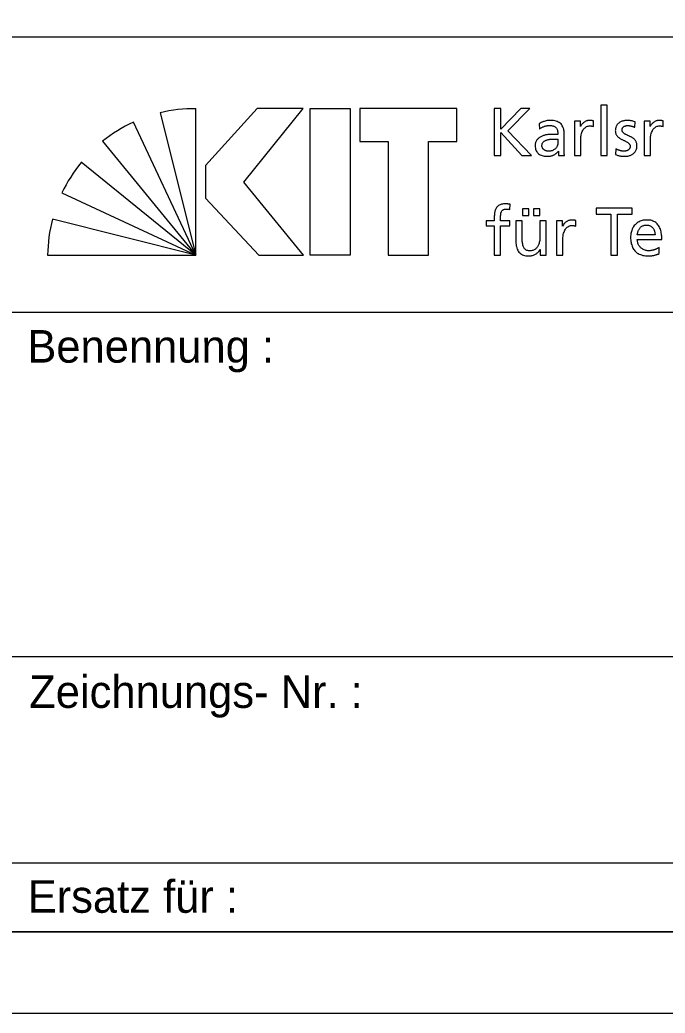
# Model space of a CAD drawing. Extents: x 0 to 594, y 0 to 420.
# Drawn here: x 550.33 to 570.16, y 0 to 30.52 of the extents above; entities that cross this region are included whole.
import ezdxf

# ---------------------------------------------------------------- set-up
doc = ezdxf.new("R2010")
doc.units = 0
doc.layers.add('90_Plankopf', color=7, linetype='Continuous')

msp = doc.modelspace()

# ---------------------------------------------------------------- linework, layer by layer
at = {"layer": '90_Plankopf'}
for p, q in [((503.06, 29.995), (592, 29.995)), ((503.06, 29.995), (592, 29.995)), ((555.74, 23.293), (555.74, 27.792)), ((564.905, 27.793), (564.905, 26.353)), ((554.637, 27.666), (555.74, 23.293)), ((555.74, 23.293), (553.817, 27.376)), ((566.29, 27.331), (566.3, 27.166)), ((567.963, 27.242), (567.963, 27.416)), ((569.228, 27.22), (569.245, 27.389)), ((570.106, 27.242), (570.106, 27.416)), ((567.059, 26.559), (567.059, 26.995)), ((552.872, 26.793), (555.74, 23.293)), ((566.865, 26.854), (566.865, 26.761)), ((568.649, 26.559), (568.638, 26.386)), ((564.905, 26.353), (565.111, 26.353)), ((565.753, 26.353), (566.054, 26.353)), ((555.74, 23.293), (552.217, 26.143)), ((551.62, 25.207), (555.74, 23.293)), ((565.387, 24.696), (565.395, 24.853)), ((555.74, 23.293), (551.329, 24.394)), ((567.413, 24.182), (567.413, 24.356)), ((569.853, 23.92), (569.308, 23.92)), ((569.308, 23.776), (570.059, 23.776)), ((569.979, 23.337), (569.979, 23.53)), ((551.182, 23.293), (555.74, 23.293)), ((550, 21.535), (592, 21.535)), ((550, 10.96), (592, 10.96)), ((550, 4.615), (592, 4.615)), ((592, 2.5), (503.06, 2.5)), ((508.9, 2.5), (592, 2.5)), ((508.9, 2.5), (592, 2.5))]:
    msp.add_line(p, q, dxfattribs=at)
for points in [[(0, 0), (594.5, 0), (594.5, 420.5), (0, 420.5)], [(12.5, 2.5), (592, 2.5), (592, 418), (12.5, 418)], [(559.033, 27.793), (557.618, 27.793), (556.036, 26.049), (556.036, 25.046), (557.669, 23.293), (559.042, 23.293), (557.211, 25.531)], [(560.485, 27.793), (560.485, 23.293), (559.251, 23.293), (559.251, 27.793)], [(560.781, 27.793), (560.781, 26.78), (561.651, 26.78), (561.651, 23.293), (562.885, 23.293), (562.885, 26.78), (563.755, 26.78), (563.755, 27.793)]]:
    msp.add_lwpolyline(points, close=True, dxfattribs=at)
for points in [[(566.054, 26.353), (565.324, 27.112), (566, 27.793), (565.726, 27.793), (565.111, 27.16), (565.111, 27.793), (564.905, 27.793)], [(568.19, 26.353), (568.384, 26.353), (568.384, 27.9), (568.19, 27.9), (568.19, 26.353)], [(567.561, 27.242), (567.557, 27.242), (567.557, 27.405), (567.375, 27.405), (567.375, 26.353), (567.569, 26.353), (567.569, 26.832)], [(569.703, 27.242), (569.699, 27.242), (569.699, 27.405), (569.518, 27.405), (569.518, 26.353), (569.712, 26.353), (569.712, 26.832)], [(565.111, 26.353), (565.111, 27.059), (565.753, 26.353)], [(566.882, 26.489), (566.886, 26.489), (566.886, 26.353), (567.067, 26.353)], [(568.495, 23.293), (568.701, 23.293), (568.701, 24.552), (569.149, 24.552), (569.149, 24.733), (568.047, 24.733), (568.047, 24.552), (568.495, 24.552), (568.495, 23.293)], [(564.912, 24.443), (564.912, 24.346), (564.665, 24.346), (564.665, 24.189), (564.912, 24.189), (564.912, 23.293), (565.106, 23.293), (565.106, 24.189), (565.385, 24.189), (565.385, 24.346), (565.106, 24.346), (565.106, 24.459)], [(565.777, 24.713), (565.777, 24.506), (565.971, 24.506), (565.971, 24.713), (565.777, 24.713)], [(566.115, 24.713), (566.115, 24.506), (566.309, 24.506), (566.309, 24.713), (566.115, 24.713)], [(565.771, 23.801), (565.771, 24.346), (565.577, 24.346), (565.577, 23.72)], [(566.507, 23.293), (566.507, 24.346), (566.313, 24.346), (566.313, 23.859)], [(567.011, 24.182), (567.007, 24.182), (567.007, 24.346), (566.825, 24.346), (566.825, 23.293), (567.019, 23.293), (567.019, 23.772)], [(566.316, 23.46), (566.32, 23.46), (566.32, 23.293), (566.507, 23.293)]]:
    msp.add_lwpolyline(points, dxfattribs=at)
for centre, start, end in [((555.724, 23.028), 89.8053, 103.1895), ((555.831, 23.059), 115.0126, 128.3968), ((555.908, 23.131), 140.7898, 154.174), ((555.946, 23.219), 165.7222, 179.1064)]:
    msp.add_arc(centre, 4.764, start, end, dxfattribs=at)
for points in [[(567.059, 26.995), (567.06, 27.09), (567.045, 27.17), (567.017, 27.235), (566.988, 27.3), (566.942, 27.348), (566.88, 27.381), (566.817, 27.413), (566.736, 27.43), (566.636, 27.43), (566.569, 27.43), (566.507, 27.42), (566.449, 27.402), (566.391, 27.384), (566.338, 27.361), (566.29, 27.331)], [(566.3, 27.166), (566.326, 27.188), (566.356, 27.207), (566.39, 27.223), (566.423, 27.239), (566.458, 27.251), (566.495, 27.26), (566.532, 27.269), (566.568, 27.273), (566.605, 27.273), (566.67, 27.273), (566.721, 27.263), (566.759, 27.243), (566.797, 27.222), (566.824, 27.191), (566.841, 27.151), (566.858, 27.11), (566.865, 27.059), (566.865, 26.999)], [(567.963, 27.416), (567.95, 27.418), (567.937, 27.421), (567.925, 27.423), (567.912, 27.425), (567.899, 27.427), (567.885, 27.428), (567.871, 27.429), (567.854, 27.43), (567.835, 27.43), (567.798, 27.43), (567.761, 27.422), (567.726, 27.406), (567.691, 27.39), (567.659, 27.368), (567.63, 27.339), (567.601, 27.311), (567.578, 27.279), (567.561, 27.242)], [(567.569, 26.832), (567.569, 26.92), (567.581, 26.996), (567.605, 27.06), (567.629, 27.124), (567.662, 27.174), (567.705, 27.208), (567.747, 27.243), (567.798, 27.26), (567.856, 27.261), (567.873, 27.261), (567.89, 27.26), (567.909, 27.257), (567.927, 27.254), (567.945, 27.249), (567.963, 27.242)], [(569.245, 27.389), (569.207, 27.4), (569.169, 27.41), (569.13, 27.418), (569.091, 27.426), (569.049, 27.43), (569.004, 27.43), (568.951, 27.43), (568.903, 27.423), (568.858, 27.41), (568.813, 27.397), (568.774, 27.377), (568.74, 27.35), (568.706, 27.323), (568.68, 27.29), (568.661, 27.249), (568.642, 27.208), (568.632, 27.161), (568.632, 27.106), (568.632, 27.064), (568.641, 27.028), (568.658, 26.997), (568.674, 26.966), (568.695, 26.94), (568.723, 26.917), (568.75, 26.895), (568.779, 26.875), (568.812, 26.857), (568.844, 26.84), (568.876, 26.824), (568.909, 26.809), (568.941, 26.793), (568.971, 26.777), (568.998, 26.761), (569.025, 26.745), (569.047, 26.727), (569.063, 26.706), (569.079, 26.686), (569.088, 26.663), (569.088, 26.636), (569.088, 26.607), (569.082, 26.584), (569.07, 26.564), (569.058, 26.545), (569.042, 26.529), (569.022, 26.518), (569.003, 26.506), (568.982, 26.498), (568.959, 26.493), (568.935, 26.487), (568.912, 26.485), (568.89, 26.485), (568.871, 26.485), (568.847, 26.488), (568.82, 26.493), (568.792, 26.499), (568.763, 26.507), (568.733, 26.518), (568.703, 26.529), (568.675, 26.543), (568.649, 26.559)], [(568.638, 26.386), (568.683, 26.363), (568.73, 26.347), (568.779, 26.339), (568.828, 26.331), (568.877, 26.327), (568.927, 26.328), (568.975, 26.328), (569.02, 26.335), (569.064, 26.348), (569.107, 26.361), (569.147, 26.381), (569.181, 26.408), (569.216, 26.435), (569.243, 26.469), (569.264, 26.51), (569.284, 26.551), (569.294, 26.6), (569.295, 26.656), (569.294, 26.704), (569.286, 26.745), (569.269, 26.778), (569.253, 26.811), (569.231, 26.84), (569.204, 26.863), (569.177, 26.886), (569.147, 26.906), (569.115, 26.922), (569.083, 26.939), (569.05, 26.954), (569.018, 26.968), (568.986, 26.983), (568.956, 26.998), (568.929, 27.013), (568.902, 27.029), (568.88, 27.047), (568.864, 27.068), (568.847, 27.089), (568.839, 27.115), (568.838, 27.145), (568.839, 27.174), (568.848, 27.198), (568.865, 27.217), (568.882, 27.236), (568.904, 27.25), (568.932, 27.259), (568.96, 27.269), (568.991, 27.273), (569.024, 27.273), (569.036, 27.273), (569.051, 27.271), (569.069, 27.269), (569.088, 27.266), (569.107, 27.261), (569.127, 27.256), (569.148, 27.251), (569.167, 27.246), (569.185, 27.239), (569.203, 27.233), (569.217, 27.226), (569.228, 27.22)], [(570.106, 27.416), (570.092, 27.418), (570.079, 27.421), (570.067, 27.423), (570.055, 27.425), (570.041, 27.427), (570.027, 27.428), (570.013, 27.429), (569.997, 27.43), (569.978, 27.43), (569.94, 27.43), (569.904, 27.422), (569.868, 27.406), (569.833, 27.39), (569.801, 27.368), (569.773, 27.339), (569.744, 27.311), (569.721, 27.279), (569.703, 27.242)], [(569.712, 26.832), (569.712, 26.92), (569.724, 26.996), (569.747, 27.06), (569.771, 27.124), (569.804, 27.174), (569.847, 27.208), (569.89, 27.243), (569.94, 27.26), (569.998, 27.261), (570.015, 27.261), (570.033, 27.26), (570.051, 27.257), (570.07, 27.254), (570.088, 27.249), (570.106, 27.242)], [(566.865, 26.999), (566.84, 27), (566.817, 27.001), (566.795, 27.001), (566.773, 27.002), (566.751, 27.003), (566.729, 27.003), (566.708, 27.003), (566.684, 27.003), (566.659, 27.003), (566.618, 27.003), (566.576, 26.999), (566.531, 26.992), (566.487, 26.985), (566.443, 26.973), (566.4, 26.957), (566.358, 26.941), (566.319, 26.919), (566.284, 26.892), (566.25, 26.866), (566.222, 26.833), (566.201, 26.794), (566.181, 26.755), (566.171, 26.709), (566.17, 26.656), (566.171, 26.58), (566.187, 26.518), (566.219, 26.469), (566.252, 26.421), (566.297, 26.385), (566.355, 26.362), (566.413, 26.339), (566.479, 26.328), (566.556, 26.328), (566.6, 26.328), (566.64, 26.334), (566.675, 26.344), (566.71, 26.355), (566.741, 26.368), (566.768, 26.384), (566.795, 26.401), (566.818, 26.419), (566.837, 26.437), (566.855, 26.455), (566.87, 26.472), (566.882, 26.489)], [(566.865, 26.761), (566.865, 26.709), (566.854, 26.661), (566.832, 26.62), (566.81, 26.578), (566.777, 26.546), (566.733, 26.522), (566.69, 26.498), (566.636, 26.485), (566.572, 26.485), (566.55, 26.485), (566.527, 26.489), (566.504, 26.496), (566.481, 26.503), (566.46, 26.514), (566.441, 26.529), (566.422, 26.543), (566.406, 26.561), (566.394, 26.582), (566.383, 26.604), (566.377, 26.628), (566.376, 26.656), (566.377, 26.693), (566.386, 26.724), (566.404, 26.749), (566.422, 26.773), (566.446, 26.793), (566.475, 26.807), (566.503, 26.822), (566.534, 26.833), (566.567, 26.841), (566.6, 26.848), (566.632, 26.853), (566.663, 26.855), (566.694, 26.858), (566.72, 26.859), (566.741, 26.858), (566.762, 26.858), (566.783, 26.858), (566.803, 26.856), (566.824, 26.855), (566.845, 26.855), (566.865, 26.854)], [(567.067, 26.353), (567.066, 26.363), (567.065, 26.377), (567.063, 26.393), (567.062, 26.411), (567.061, 26.433), (567.061, 26.46), (567.06, 26.486), (567.059, 26.52), (567.059, 26.559)], [(565.395, 24.853), (565.375, 24.856), (565.355, 24.859), (565.334, 24.862), (565.312, 24.864), (565.29, 24.866), (565.265, 24.866), (565.194, 24.865), (565.135, 24.855), (565.089, 24.836), (565.043, 24.816), (565.007, 24.787), (564.981, 24.75), (564.955, 24.713), (564.937, 24.668), (564.927, 24.616), (564.917, 24.565), (564.912, 24.507), (564.912, 24.443)], [(565.106, 24.459), (565.106, 24.495), (565.108, 24.528), (565.112, 24.558), (565.116, 24.588), (565.125, 24.615), (565.137, 24.637), (565.15, 24.66), (565.169, 24.677), (565.194, 24.69), (565.219, 24.702), (565.252, 24.709), (565.294, 24.709), (565.311, 24.709), (565.328, 24.708), (565.344, 24.706), (565.361, 24.703), (565.375, 24.7), (565.387, 24.696)], [(567.413, 24.356), (567.4, 24.359), (567.387, 24.361), (567.375, 24.363), (567.363, 24.365), (567.349, 24.367), (567.335, 24.368), (567.321, 24.37), (567.304, 24.37), (567.286, 24.37), (567.248, 24.37), (567.212, 24.362), (567.176, 24.346), (567.141, 24.33), (567.109, 24.308), (567.081, 24.28), (567.052, 24.252), (567.029, 24.219), (567.011, 24.182)], [(567.019, 23.772), (567.02, 23.86), (567.032, 23.937), (567.055, 24.001), (567.079, 24.065), (567.112, 24.114), (567.155, 24.148), (567.198, 24.183), (567.248, 24.201), (567.306, 24.201), (567.323, 24.201), (567.341, 24.2), (567.359, 24.197), (567.378, 24.195), (567.396, 24.19), (567.413, 24.182)], [(570.059, 23.776), (570.06, 23.861), (570.052, 23.94), (570.036, 24.012), (570.02, 24.084), (569.995, 24.146), (569.959, 24.2), (569.923, 24.254), (569.875, 24.295), (569.815, 24.325), (569.756, 24.355), (569.682, 24.37), (569.595, 24.37), (569.52, 24.37), (569.453, 24.357), (569.392, 24.331), (569.332, 24.305), (569.28, 24.269), (569.237, 24.221), (569.194, 24.174), (569.16, 24.118), (569.137, 24.052), (569.114, 23.988), (569.102, 23.916), (569.102, 23.838), (569.102, 23.752), (569.113, 23.674), (569.134, 23.604), (569.156, 23.535), (569.19, 23.475), (569.234, 23.425), (569.279, 23.375), (569.335, 23.336), (569.404, 23.309), (569.473, 23.282), (569.553, 23.269), (569.647, 23.268), (569.704, 23.269), (569.753, 23.273), (569.793, 23.28), (569.834, 23.288), (569.869, 23.297), (569.898, 23.307), (569.928, 23.317), (569.954, 23.327), (569.979, 23.337)], [(569.308, 23.92), (569.312, 23.955), (569.32, 23.989), (569.332, 24.024), (569.344, 24.058), (569.361, 24.089), (569.384, 24.118), (569.406, 24.147), (569.434, 24.17), (569.469, 24.187), (569.503, 24.204), (569.543, 24.213), (569.591, 24.213), (569.633, 24.213), (569.67, 24.206), (569.702, 24.19), (569.735, 24.175), (569.762, 24.154), (569.785, 24.127), (569.807, 24.101), (569.824, 24.069), (569.835, 24.034), (569.847, 23.999), (569.853, 23.961), (569.853, 23.92)], [(566.313, 23.859), (566.313, 23.794), (566.307, 23.736), (566.295, 23.683), (566.282, 23.63), (566.263, 23.584), (566.236, 23.546), (566.21, 23.507), (566.177, 23.478), (566.137, 23.457), (566.096, 23.436), (566.049, 23.426), (565.994, 23.425), (565.938, 23.429), (565.893, 23.444), (565.861, 23.473), (565.828, 23.501), (565.805, 23.542), (565.791, 23.597), (565.777, 23.651), (565.771, 23.719), (565.771, 23.801)], [(565.577, 23.72), (565.577, 23.626), (565.591, 23.545), (565.618, 23.478), (565.646, 23.41), (565.69, 23.359), (565.748, 23.323), (565.806, 23.287), (565.88, 23.269), (565.971, 23.268), (566.02, 23.269), (566.068, 23.276), (566.113, 23.291), (566.158, 23.307), (566.198, 23.329), (566.233, 23.357), (566.268, 23.386), (566.296, 23.42), (566.316, 23.46)], [(569.979, 23.53), (569.967, 23.521), (569.949, 23.51), (569.926, 23.497), (569.903, 23.485), (569.877, 23.474), (569.847, 23.463), (569.817, 23.452), (569.786, 23.443), (569.753, 23.436), (569.72, 23.429), (569.687, 23.426), (569.655, 23.425), (569.608, 23.426), (569.565, 23.434), (569.523, 23.451), (569.482, 23.468), (569.445, 23.492), (569.413, 23.523), (569.38, 23.554), (569.355, 23.59), (569.336, 23.633), (569.318, 23.676), (569.309, 23.724), (569.308, 23.776)]]:
    msp.add_open_spline(points, degree=3, dxfattribs=at)

# ---------------------------------------------------------------- texts
for s, p in [('Benennung :', (550.557, 19.989)), ('Zeichnungs- Nr. :', (550.614, 9.379)), ('Ersatz für :', (550.569, 3.084))]:
    msp.add_text(s, height=1, dxfattribs=at).set_placement(p)

doc.saveas('drawing.dxf')
